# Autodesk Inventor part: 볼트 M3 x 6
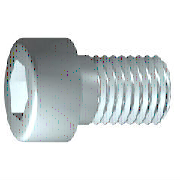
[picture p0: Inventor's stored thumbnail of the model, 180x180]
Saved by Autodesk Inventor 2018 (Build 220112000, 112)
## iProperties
IsCustomPart: 1
Created: 2012-02
Part Number: 볼트 M3 x 6
Material: 강철, 연강
Description: 원통형 머리 캡 나사
Document SubType Name: Modeling
Standard: JIS B 1176
Designer: mdu-01
Standards Organization: JIS
Language: ko-KR
Size Designation: M3 x 6
Categories: <MemberInstance><Categories><Category DisplayName="조임쇠" InternalName="e4da775c-781d-43d5-af7c-5136215cf5a6" Mnemonic="FSTN"><Category DisplayName="볼트" InternalN
Density: 1 g/cm^3
Appearance: 강철
Author: mdu-01
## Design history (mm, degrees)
sketch "스케치1"
  geometry: L1 (-0.867, 0)-(6, 0); L2 (6, 0)-(6, 1.5); L3 (6, 1.5)-(1.25, 1.5); L4 (1.25, 1.5)-(0.943, 1.5); L5 (0.943, 1.5)-(0, 1.5); L6 (0, 1.5)-(0, 2.75); L7 (0, 2.75)-(-3, 2.75); L8 (-3, 2.75)-(-3, 1.443); L9 (-3, 1.443)-(-1.7, 1.443); L10 (-1.7, 1.443)-(-0.867, 0); L11 (-4.8, 0)-(7.8, 0) reference; L12 (0, -0.55)-(0, 3.3) reference; L13 (1.25, 1.5)-(0, 1.5)
  constraints: 22 end point, 6 parallel, 2 collinear, 2 perpendicular, 1 horizontal, 1 point on line
  dimensions: "d1" = 4.75 distance from line of L3.end L2 (= GEL); "d2" = 0.30683 distance of L4.end L3.end (computed from GAL); "d3" = 3 distance between parallel lines of L8 L6 (= KOH); "d4" = 1.3 distance of L8.end L9.end (= INTI); "d5" = 60 deg angle of L10 L1; "d6" = 3 diameter of L3 L1 (= GD); "d7" = 3 diameter of L5 L1 (= BDM); "d8" = 2.88675 diameter of L9 L1 (= 1.1547 x SW); "d9" = 5.5 diameter of L7 L1 (= KOD); "d26" = 6 distance between parallel lines of L12 L2 (= NLG)
revolve "본체" sketch "스케치1" stored, may be unused: angle "d10" = 90 deg
sketch "스케치2"
  geometry: L1 (0, -3.85)-(0, 3.85) reference; L2 (-3.85, 0)-(3.85, 0) reference; L3 (1.443, 0)-(0.722, -1.25); L4 (0.722, -1.25)-(-0.722, -1.25); L5 (-0.722, -1.25)-(-1.443, 0); L6 (-1.443, 0)-(-0.722, 1.25); L7 (-0.722, 1.25)-(0.722, 1.25); L8 (0.722, 1.25)-(1.443, 0); 2 further points
  constraints: 12 end point, 1 coincident, 1 horizontal alignment, 1 point on line, 12 other
extrude "슬롯" join sketch "스케치2" stored distance "d11" = 10; taper "d12" = 0 deg
workplane "Work Plane1"
fillet "Fillet2" dims "d30" = 0.1 (= R)
body "Solid1"
fillet "모깎기1" dims "d17" = 0.3 (= RR)
feature "스레드" dims "d13" = 4.75 (= GEL), "d14" = 0
chamfer "모따기1" distance "d15" = 0.30673 (= -0.5 x SPD + 0.5 x GD); stored, may be unused: second distance "d16" = 0.30673 (= GUL), angle "d27" = 45 deg
other parameters: "GD" = 3 (= NND) [user parameter; used in 2 equation terms], "NLG" = 6 [user parameter; used in 1 equation term], "GEL" = 4.75 [user parameter; used in 2 equation terms], "KOD" = 5.5 [user parameter; used in 1 equation term], "KOH" = 3 [user parameter; used in 1 equation term], "INTI" = 1.3 [user parameter; used in 1 equation term], "GAL" = 0.30673 (= 0.61345 x PTC) [user parameter; used in 1 equation term], "GUL" = 0.30673 (= 0.61345 x PTC) [user parameter; used in 1 equation term], "BDM" = 3 (= NND) [user parameter; used in 1 equation term], "SW" = 2.5 [user parameter; used in 2 equation terms], "RR" = 0.3 [user parameter; used in 1 equation term], "SPD" = 2.38655 (= NND - 1.2269 x PTC) [user parameter; used in 1 equation term], "d19" = 0, "d28" = 0, "d29" = 0, "R" = 0.1 [user parameter; used in 1 equation term], "PHH" = 0.1 [user parameter], "GD1" = 2.38655 (= THREADDIA - 1.2269 x PTC) [user parameter], "THREADDIA" = 3 [user parameter; used in 1 equation term], "FAWI" = 45 deg [user parameter], "PTC" = 0.5 [user parameter; used in 5 equation terms], "NND" = 3 [user parameter; used in 3 equation terms], "TOA" = 30 deg [user parameter], "E0" = 2.8875 (= 1.155 x SW) [user parameter]
